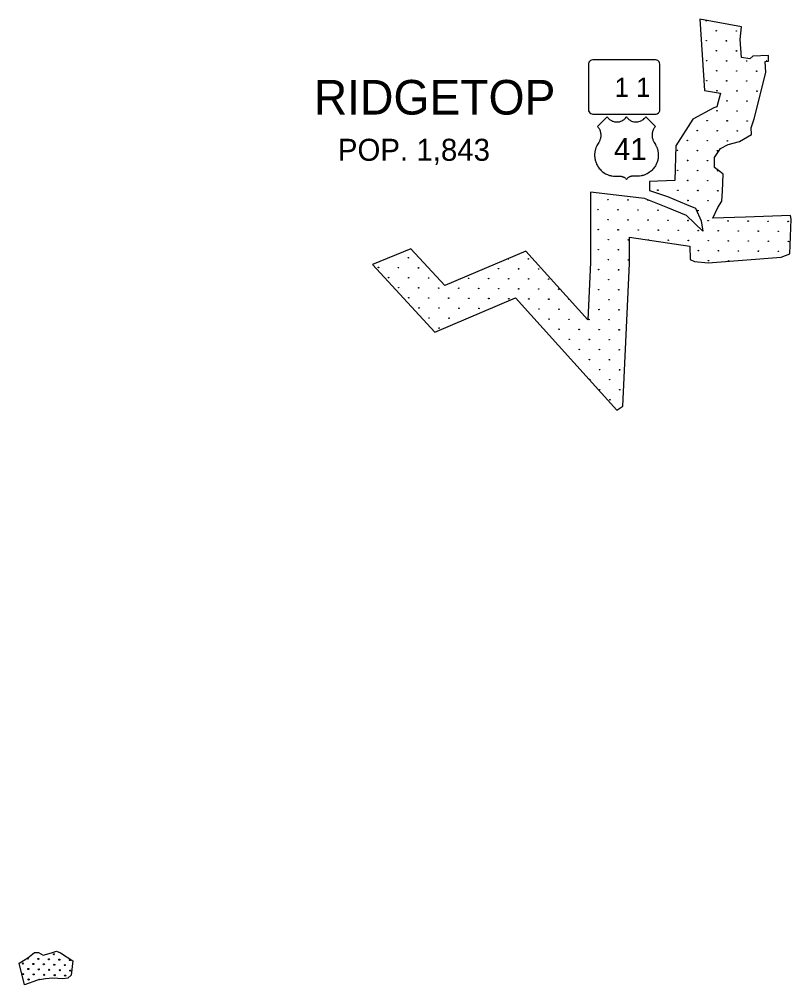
# Model space of a CAD drawing. Extents: x 1612280 to 1883141, y 560852 to 780851.
# Drawn here: x 1730295 to 1745083, y 736836 to 755396 of the extents above; entities that cross this region are included whole.
import ezdxf

# ---------------------------------------------------------------- set-up
doc = ezdxf.new("R2010")
doc.units = 0
for name, color, linetype in [('DESIGN - EROSION CONTROL - Devices', 7, 'Continuous'), ('DESIGN - ROW - Slope Lines', 7, 'Continuous'), ('DESIGN - SCRATCH - User 1', 7, 'Continuous'), ('DESIGN - TRAFFIC CONTROL PERMANENT - Pavement Marking Text', 7, 'Continuous'), ('SURVEY - DRAINAGE - Bridge Deck with Text', 7, 'Continuous'), ('SURVEY - VEGETATION - Features with Text', 7, 'Continuous')]:
    doc.layers.add(name, color=color, linetype=linetype)

msp = doc.modelspace()

# ---------------------------------------------------------------- linework, layer by layer
at = {"layer": 'DESIGN - EROSION CONTROL - Devices'}
for centre in [(1743691, 755176), (1743691, 755176), (1744076, 755172), (1744076, 755172), (1743501, 754986), (1743501, 754986), (1743886, 754982), (1743886, 754982), (1743695, 754791), (1743695, 754791), (1744080, 754788), (1744080, 754788), (1743505, 754601), (1743505, 754601), (1743889, 754597), (1743889, 754597), (1744274, 754594), (1744274, 754594), (1743699, 754407), (1743699, 754407), (1744084, 754403), (1744084, 754403), (1744468, 754399), (1744468, 754399), (1743509, 754217), (1743509, 754217), (1743893, 754213), (1743893, 754213), (1744278, 754209), (1744278, 754209), (1743703, 754022), (1743703, 754022), (1744087, 754019), (1744087, 754019), (1744472, 754015), (1744472, 754015), (1743897, 753828), (1743897, 753828), (1744281, 753824), (1744281, 753824), (1743706, 753638), (1743706, 753638), (1744091, 753634), (1744091, 753634), (1743516, 753447), (1743516, 753447), (1743901, 753444), (1743901, 753444), (1744285, 753440), (1744285, 753440), (1743326, 753257), (1743326, 753257), (1743710, 753253), (1743710, 753253), (1744095, 753250), (1744095, 753250), (1743135, 753067), (1743135, 753067), (1743520, 753063), (1743520, 753063), (1743904, 753059), (1743904, 753059), (1742945, 752876), (1742945, 752876), (1743329, 752872), (1743329, 752872), (1743714, 752869), (1743714, 752869), (1743139, 752682), (1743139, 752682), (1743523, 752678), (1743523, 752678), (1742949, 752492), (1742949, 752492), (1743333, 752488), (1743333, 752488), (1743718, 752484), (1743718, 752484), (1743143, 752297), (1743143, 752297), (1743527, 752294), (1743527, 752294), (1742568, 752111), (1742568, 752111), (1742952, 752107), (1742952, 752107), (1743337, 752103), (1743337, 752103), (1743721, 752100), (1743721, 752100), (1741608, 751928), (1741608, 751928), (1741993, 751924), (1741993, 751924), (1743146, 751913), (1743146, 751913), (1743531, 751909), (1743531, 751909), (1741418, 751737), (1741418, 751737), (1741802, 751734), (1741802, 751734), (1742187, 751730), (1742187, 751730), (1742571, 751726), (1742571, 751726), (1743341, 751719), (1743341, 751719), (1741612, 751543), (1741612, 751543), (1741996, 751540), (1741996, 751540), (1742381, 751536), (1742381, 751536), (1742766, 751532), (1742766, 751532), (1743150, 751528), (1743150, 751528), (1743535, 751525), (1743535, 751525), (1743919, 751521), (1743919, 751521), (1744304, 751517), (1744304, 751517), (1741422, 751353), (1741422, 751353), (1741806, 751349), (1741806, 751349), (1742191, 751345), (1742191, 751345), (1742575, 751342), (1742575, 751342), (1742960, 751338), (1742960, 751338), (1743344, 751334), (1743344, 751334), (1743729, 751331), (1743729, 751331), (1744688, 751513), (1744688, 751513), (1745073, 751510), (1745073, 751510), (1741616, 751159), (1741616, 751159), (1742000, 751155), (1742000, 751155), (1742769, 751148), (1742769, 751148), (1744113, 751327), (1744113, 751327), (1744498, 751323), (1744498, 751323), (1744882, 751319), (1744882, 751319), (1741425, 750968), (1741425, 750968), (1741810, 750965), (1741810, 750965), (1743154, 751144), (1743154, 751144), (1743538, 751140), (1743538, 751140), (1743923, 751136), (1743923, 751136), (1744308, 751133), (1744308, 751133), (1744692, 751129), (1744692, 751129), (1745077, 751125), (1745077, 751125), (1737774, 750812), (1737774, 750812), (1740081, 750789), (1740081, 750789), (1741619, 750774), (1741619, 750774), (1743348, 750950), (1743348, 750950), (1743733, 750946), (1743733, 750946), (1744117, 750942), (1744117, 750942), (1744502, 750938), (1744502, 750938), (1744886, 750935), (1744886, 750935), (1737199, 750625), (1737199, 750625), (1737583, 750621), (1737583, 750621), (1737968, 750617), (1737968, 750617), (1739506, 750602), (1739506, 750602), (1739891, 750599), (1739891, 750599), (1740275, 750595), (1740275, 750595), (1742004, 750770), (1742004, 750770), (1743542, 750756), (1743542, 750756), (1743927, 750752), (1743927, 750752), (1737393, 750431), (1737393, 750431), (1737778, 750427), (1737778, 750427), (1738162, 750423), (1738162, 750423), (1738931, 750416), (1738931, 750416), (1739316, 750412), (1739316, 750412), (1739700, 750408), (1739700, 750408), (1740085, 750405), (1740085, 750405), (1741429, 750584), (1741429, 750584), (1741814, 750580), (1741814, 750580), (1737587, 750237), (1737587, 750237), (1737972, 750233), (1737972, 750233), (1738356, 750229), (1738356, 750229), (1738741, 750225), (1738741, 750225), (1739125, 750222), (1739125, 750222), (1739510, 750218), (1739510, 750218), (1740469, 750401), (1740469, 750401), (1741623, 750390), (1741623, 750390), (1737781, 750042), (1737781, 750042), (1738166, 750039), (1738166, 750039), (1738550, 750035), (1738550, 750035), (1738935, 750031), (1738935, 750031), (1739895, 750214), (1739895, 750214), (1740279, 750210), (1740279, 750210), (1740664, 750207), (1740664, 750207), (1741433, 750199), (1741433, 750199), (1741817, 750196), (1741817, 750196), (1737975, 749848), (1737975, 749848), (1739320, 750028), (1739320, 750028), (1739704, 750024), (1739704, 750024), (1740089, 750020), (1740089, 750020), (1740473, 750016), (1740473, 750016), (1740858, 750013), (1740858, 750013), (1741627, 750005), (1741627, 750005), (1738360, 749845), (1738360, 749845), (1738745, 749841), (1738745, 749841), (1739129, 749837), (1739129, 749837), (1740283, 749826), (1740283, 749826), (1740667, 749822), (1740667, 749822), (1741436, 749815), (1741436, 749815), (1741821, 749811), (1741821, 749811), (1738170, 749654), (1738170, 749654), (1738554, 749650), (1738554, 749650), (1740477, 749632), (1740477, 749632), (1740861, 749628), (1740861, 749628), (1741246, 749624), (1741246, 749624), (1741631, 749621), (1741631, 749621), (1738364, 749460), (1738364, 749460), (1740671, 749438), (1740671, 749438), (1741056, 749434), (1741056, 749434), (1741440, 749430), (1741440, 749430), (1741825, 749426), (1741825, 749426), (1740865, 749243), (1740865, 749243), (1741250, 749240), (1741250, 749240), (1741634, 749236), (1741634, 749236), (1741059, 749049), (1741059, 749049), (1741444, 749046), (1741444, 749046), (1741828, 749042), (1741828, 749042), (1741254, 748855), (1741254, 748855), (1741638, 748851), (1741638, 748851), (1741448, 748661), (1741448, 748661), (1741832, 748657), (1741832, 748657), (1741257, 748471), (1741257, 748471), (1741642, 748467), (1741642, 748467), (1741451, 748276), (1741451, 748276), (1741836, 748273), (1741836, 748273), (1741646, 748082), (1741646, 748082)]:
    msp.add_circle(centre, 5.28, dxfattribs=at)
for centre, start, end in [((1743497, 755370), 124.9794, 34.3953), ((1744658, 754590), 346.4464, 212.4916), ((1742377, 751920), 135.8108, 1.6207), ((1742385, 751151), 2.3635, 161.1221), ((1739697, 750793), 175.2551, 50.7454), ((1742008, 750386), 59.5384, 295.1692), ((1741242, 750009), 263.3295, 91.3777)]:
    msp.add_arc(centre, 5.28, start, end, dxfattribs=at)
at = {"layer": 'DESIGN - ROW - Slope Lines'}
for p, q in [((1741233, 754515), (1741233, 753683)), ((1741233, 754515), (1741233, 753683)), ((1742495, 754616), (1741339, 754616)), ((1742495, 754616), (1741339, 754616)), ((1742606, 753685), (1742606, 754505)), ((1742606, 753685), (1742606, 754505)), ((1741340, 753574), (1742496, 753574)), ((1741340, 753574), (1742496, 753574))]:
    msp.add_line(p, q, dxfattribs=at)
for centre, radius, start, end in [((1741446, 754516), 213, 169.2361, 180.3208), ((1741446, 754516), 213, 169.2361, 180.3208), ((1741322, 754528), 89.8, 108.3711, 161.4494), ((1741322, 754528), 89.8, 108.3711, 161.4494), ((1741329, 754456), 160, 86.6485, 102.7002), ((1741329, 754456), 160, 86.6485, 102.7002), ((1742505, 754418), 198, 77.6972, 92.6427), ((1742505, 754418), 198, 77.6972, 92.6427), ((1742517, 754527), 90.3, 20.2625, 70.5274), ((1742517, 754527), 90.3, 20.2625, 70.5274), ((1742353, 754509), 254, 359.0166, 11.1674), ((1742353, 754509), 254, 359.0166, 11.1674), ((1741507, 753683), 274, 179.8527, 189.8963), ((1741507, 753683), 274, 179.8527, 189.8963), ((1741324, 753665), 91.3, 198.5723, 254.4317), ((1741324, 753665), 91.3, 198.5723, 254.4317), ((1741344, 753936), 362, 263.0109, 269.3986), ((1741344, 753936), 362, 263.0109, 269.3986), ((1742507, 754109), 535, 268.8795, 272.9942), ((1742507, 754109), 535, 268.8795, 272.9942), ((1742518, 753662), 89.4, 280.9255, 342.7445), ((1742518, 753662), 89.4, 280.9255, 342.7445), ((1742537, 753654), 68.6, 345.0701, 358.7436), ((1742537, 753654), 68.6, 345.0701, 358.7436), ((1741659, 753690), 947, 357.7373, 359.7127), ((1741659, 753690), 947, 357.7373, 359.7127)]:
    msp.add_arc(centre, radius, start, end, dxfattribs=at)
at = {"layer": 'DESIGN - SCRATCH - User 1'}
for points in [[(1743375, 755396), (1743468, 754029), (1743772, 753975), (1743705, 753711), (1743642, 753694), (1743242, 753478), (1742917, 752965), (1742897, 752294)], [(1743375, 755396), (1743468, 754029), (1743772, 753975), (1743705, 753711), (1743642, 753694), (1743242, 753478), (1742917, 752965), (1742897, 752294)], [(1743654, 752545), (1743660, 752737), (1743770, 752911), (1743921, 752992), (1744136, 753050), (1744368, 753184), (1744362, 753312), (1744420, 753480), (1744646, 754374), (1744629, 754583), (1744698, 754594), (1744698, 754699), (1744397, 754687), (1744339, 754635), (1744176, 754664), (1744153, 755007), (1744176, 755250), (1743375, 755396)], [(1743654, 752545), (1743660, 752737), (1743770, 752911), (1743921, 752992), (1744136, 753050), (1744368, 753184), (1744362, 753312), (1744420, 753480), (1744646, 754374), (1744629, 754583), (1744698, 754594), (1744698, 754699), (1744397, 754687), (1744339, 754635), (1744176, 754664), (1744153, 755007), (1744176, 755250), (1743375, 755396)], [(1742025, 751205), (1743185, 751036), (1743190, 750781), (1743272, 750740), (1743533, 750711), (1744936, 750821), (1745104, 750885), (1745133, 751553), (1745116, 751622), (1744252, 751593), (1743625, 751570), (1743724, 751779), (1743799, 751901), (1743811, 752093), (1743823, 752418), (1743759, 752470), (1743654, 752545)], [(1742025, 751205), (1743185, 751036), (1743190, 750781), (1743272, 750740), (1743533, 750711), (1744936, 750821), (1745104, 750885), (1745133, 751553), (1745116, 751622), (1744252, 751593), (1743625, 751570), (1743724, 751779), (1743799, 751901), (1743811, 752093), (1743823, 752418), (1743759, 752470), (1743654, 752545)], [(1742897, 752294), (1742406, 752276), (1742410, 752105)], [(1742897, 752294), (1742406, 752276), (1742410, 752105)], [(1742410, 752105), (1742753, 751990), (1743122, 751836), (1743291, 751767), (1743399, 751522), (1743432, 751323)], [(1742410, 752105), (1742753, 751990), (1743122, 751836), (1743291, 751767), (1743399, 751522), (1743432, 751323)], [(1741275, 752071), (1741275, 750721), (1741224, 749617), (1740033, 750938)], [(1741275, 752071), (1741275, 750721), (1741224, 749617), (1740033, 750938)], [(1743432, 751323), (1743119, 751625), (1742762, 751773), (1742313, 751948), (1741275, 752071)], [(1743432, 751323), (1743119, 751625), (1742762, 751773), (1742313, 751948), (1741275, 752071)], [(1739834, 750039), (1741777, 747883), (1741898, 747961), (1742025, 750703), (1742025, 751205)], [(1739834, 750039), (1741777, 747883), (1741898, 747961), (1742025, 750703), (1742025, 751205)], [(1737820, 750986), (1737083, 750679)], [(1737820, 750986), (1737083, 750679)], [(1738475, 750277), (1737820, 750986)], [(1738475, 750277), (1737820, 750986)], [(1740033, 750938), (1738475, 750277)], [(1740033, 750938), (1738475, 750277)], [(1737083, 750679), (1738283, 749381)], [(1737083, 750679), (1738283, 749381)], [(1738283, 749381), (1739834, 750039)], [(1738283, 749381), (1739834, 750039)], [(1730295, 737251), (1730457, 737355), (1730585, 737454), (1730665, 737454), (1730754, 737403), (1730916, 737451), (1731012, 737483), (1731089, 737449), (1731326, 737294)], [(1730295, 737251), (1730457, 737355), (1730585, 737454), (1730665, 737454), (1730754, 737403), (1730916, 737451), (1731012, 737483), (1731089, 737449), (1731326, 737294)], [(1730397, 736836), (1730295, 737251)], [(1730397, 736836), (1730295, 737251)], [(1731326, 737294), (1731292, 737017), (1731227, 736961), (1731130, 736947), (1730937, 736959), (1730797, 736949), (1730643, 736920), (1730397, 736836)], [(1731326, 737294), (1731292, 737017), (1731227, 736961), (1731130, 736947), (1730937, 736959), (1730797, 736949), (1730643, 736920), (1730397, 736836)]]:
    msp.add_lwpolyline(points, dxfattribs=at)
msp.add_arc((1731162, 737413), 10.6, 224.4965, 249.1768, dxfattribs=at)
at = {"layer": 'DESIGN - TRAFFIC CONTROL PERMANENT - Pavement Marking Text'}
for centre in [(1730961, 737421), (1730961, 737421), (1730363, 737242), (1730363, 737242), (1730460, 737339), (1730460, 737339), (1730565, 737234), (1730565, 737234), (1730662, 737331), (1730662, 737331), (1730767, 737227), (1730767, 737227), (1730864, 737324), (1730864, 737324), (1730968, 737219), (1730968, 737219), (1731065, 737316), (1731065, 737316), (1731267, 737309), (1731267, 737309), (1730371, 737040), (1730371, 737040), (1730468, 737137), (1730468, 737137), (1730669, 737130), (1730669, 737130), (1730871, 737122), (1730871, 737122), (1731073, 737115), (1731073, 737115), (1731170, 737212), (1731170, 737212), (1731274, 737107), (1731274, 737107), (1730475, 736935), (1730475, 736935), (1730572, 737033), (1730572, 737033), (1730774, 737025), (1730774, 737025), (1730976, 737018), (1730976, 737018), (1731177, 737010), (1731177, 737010)]:
    msp.add_circle(centre, 10.6, dxfattribs=at)
for centre, start, end in [((1730557, 737436), 233.0295, 22.4541), ((1730677, 736928), 1.938, 199.3172)]:
    msp.add_arc(centre, 10.6, start, end, dxfattribs=at)
at = {"layer": 'SURVEY - DRAINAGE - Bridge Deck with Text'}
for points in [[(1741407, 753337), (1741594, 753523), (1741604, 753509), (1741616, 753495), (1741628, 753482), (1741639, 753473), (1741652, 753463), (1741665, 753455), (1741677, 753448), (1741692, 753441), (1741705, 753436), (1741721, 753430), (1741737, 753427), (1741753, 753424), (1741771, 753423), (1741779, 753423), (1741787, 753423), (1741795, 753423), (1741805, 753424), (1741815, 753426), (1741829, 753428), (1741841, 753431), (1741860, 753437), (1741877, 753445), (1741893, 753454), (1741907, 753463), (1741921, 753473), (1741934, 753485), (1741946, 753498), (1741957, 753512), (1741965, 753523), (1741972, 753513), (1741981, 753502), (1741989, 753493), (1741998, 753484), (1742010, 753473), (1742022, 753464), (1742035, 753455), (1742049, 753447), (1742065, 753440), (1742084, 753433), (1742105, 753427), (1742126, 753424), (1742144, 753423), (1742164, 753423), (1742184, 753425), (1742204, 753429), (1742226, 753436), (1742244, 753443), (1742259, 753451), (1742276, 753461), (1742290, 753472), (1742306, 753486), (1742317, 753497), (1742326, 753509), (1742336, 753523), (1742523, 753337)], [(1741407, 753337), (1741594, 753523), (1741604, 753509), (1741616, 753495), (1741628, 753482), (1741639, 753473), (1741652, 753463), (1741665, 753455), (1741677, 753448), (1741692, 753441), (1741705, 753436), (1741721, 753430), (1741737, 753427), (1741753, 753424), (1741771, 753423), (1741779, 753423), (1741787, 753423), (1741795, 753423), (1741805, 753424), (1741815, 753426), (1741829, 753428), (1741841, 753431), (1741860, 753437), (1741877, 753445), (1741893, 753454), (1741907, 753463), (1741921, 753473), (1741934, 753485), (1741946, 753498), (1741957, 753512), (1741965, 753523), (1741972, 753513), (1741981, 753502), (1741989, 753493), (1741998, 753484), (1742010, 753473), (1742022, 753464), (1742035, 753455), (1742049, 753447), (1742065, 753440), (1742084, 753433), (1742105, 753427), (1742126, 753424), (1742144, 753423), (1742164, 753423), (1742184, 753425), (1742204, 753429), (1742226, 753436), (1742244, 753443), (1742259, 753451), (1742276, 753461), (1742290, 753472), (1742306, 753486), (1742317, 753497), (1742326, 753509), (1742336, 753523), (1742523, 753337)], [(1741407, 753337), (1741416, 753326), (1741424, 753315), (1741432, 753304), (1741438, 753294), (1741445, 753281), (1741451, 753268), (1741457, 753254), (1741462, 753238), (1741466, 753224), (1741469, 753208), (1741471, 753190), (1741472, 753168), (1741472, 753152), (1741471, 753136), (1741469, 753122), (1741465, 753104), (1741461, 753090), (1741456, 753077), (1741451, 753065), (1741446, 753054), (1741439, 753041), (1741431, 753028), (1741421, 753010), (1741408, 752989), (1741404, 752983), (1741399, 752972), (1741392, 752959), (1741388, 752950), (1741383, 752939), (1741379, 752928), (1741375, 752917), (1741371, 752906), (1741367, 752893), (1741364, 752880), (1741361, 752868), (1741359, 752856), (1741357, 752844), (1741355, 752832), (1741354, 752820), (1741353, 752809), (1741353, 752798), (1741353, 752787), (1741353, 752774), (1741353, 752763), (1741354, 752748), (1741356, 752733), (1741358, 752718), (1741361, 752703), (1741365, 752687), (1741370, 752668), (1741375, 752653), (1741381, 752635), (1741387, 752622), (1741392, 752610), (1741399, 752595), (1741409, 752578), (1741418, 752563), (1741430, 752546), (1741443, 752529), (1741457, 752513), (1741471, 752498), (1741484, 752486), (1741501, 752471), (1741520, 752456), (1741544, 752439), (1741565, 752428), (1741584, 752418), (1741602, 752410), (1741623, 752402), (1741642, 752395), (1741662, 752390), (1741672, 752388), (1741684, 752386), (1741714, 752383), (1741820, 752380), (1741868, 752378), (1741872, 752377), (1741877, 752376), (1741882, 752375), (1741887, 752373), (1741892, 752372), (1741896, 752370), (1741902, 752368), (1741906, 752366), (1741911, 752363), (1741915, 752361), (1741919, 752359), (1741928, 752354), (1741937, 752347), (1741945, 752339), (1741953, 752332), (1741959, 752325), (1741965, 752316)], [(1741407, 753337), (1741416, 753326), (1741424, 753315), (1741432, 753304), (1741438, 753294), (1741445, 753281), (1741451, 753268), (1741457, 753254), (1741462, 753238), (1741466, 753224), (1741469, 753208), (1741471, 753190), (1741472, 753168), (1741472, 753152), (1741471, 753136), (1741469, 753122), (1741465, 753104), (1741461, 753090), (1741456, 753077), (1741451, 753065), (1741446, 753054), (1741439, 753041), (1741431, 753028), (1741421, 753010), (1741408, 752989), (1741404, 752983), (1741399, 752972), (1741392, 752959), (1741388, 752950), (1741383, 752939), (1741379, 752928), (1741375, 752917), (1741371, 752906), (1741367, 752893), (1741364, 752880), (1741361, 752868), (1741359, 752856), (1741357, 752844), (1741355, 752832), (1741354, 752820), (1741353, 752809), (1741353, 752798), (1741353, 752787), (1741353, 752774), (1741353, 752763), (1741354, 752748), (1741356, 752733), (1741358, 752718), (1741361, 752703), (1741365, 752687), (1741370, 752668), (1741375, 752653), (1741381, 752635), (1741387, 752622), (1741392, 752610), (1741399, 752595), (1741409, 752578), (1741418, 752563), (1741430, 752546), (1741443, 752529), (1741457, 752513), (1741471, 752498), (1741484, 752486), (1741501, 752471), (1741520, 752456), (1741544, 752439), (1741565, 752428), (1741584, 752418), (1741602, 752410), (1741623, 752402), (1741642, 752395), (1741662, 752390), (1741672, 752388), (1741684, 752386), (1741714, 752383), (1741820, 752380), (1741868, 752378), (1741872, 752377), (1741877, 752376), (1741882, 752375), (1741887, 752373), (1741892, 752372), (1741896, 752370), (1741902, 752368), (1741906, 752366), (1741911, 752363), (1741915, 752361), (1741919, 752359), (1741928, 752354), (1741937, 752347), (1741945, 752339), (1741953, 752332), (1741959, 752325), (1741965, 752316)], [(1742523, 753337), (1742514, 753326), (1742506, 753315), (1742498, 753304), (1742492, 753294), (1742485, 753282), (1742479, 753268), (1742473, 753254), (1742468, 753238), (1742464, 753224), (1742461, 753208), (1742459, 753190), (1742458, 753168), (1742458, 753152), (1742459, 753136), (1742461, 753122), (1742465, 753104), (1742469, 753090), (1742474, 753077), (1742479, 753065), (1742483, 753054), (1742491, 753041), (1742498, 753028), (1742509, 753010), (1742522, 752989), (1742525, 752983), (1742531, 752972), (1742538, 752959), (1742542, 752950), (1742547, 752939), (1742551, 752928), (1742555, 752917), (1742559, 752906), (1742563, 752893), (1742566, 752880), (1742569, 752868), (1742571, 752856), (1742573, 752844), (1742575, 752832), (1742576, 752820), (1742577, 752809), (1742577, 752798), (1742577, 752787), (1742577, 752774), (1742577, 752763), (1742576, 752748), (1742574, 752733), (1742572, 752718), (1742569, 752703), (1742565, 752687), (1742560, 752668), (1742555, 752653), (1742549, 752635), (1742543, 752622), (1742538, 752610), (1742531, 752595), (1742521, 752578), (1742512, 752563), (1742500, 752546), (1742487, 752529), (1742473, 752513), (1742459, 752498), (1742446, 752486), (1742429, 752471), (1742410, 752456), (1742385, 752439), (1742365, 752428), (1742346, 752418), (1742328, 752410), (1742307, 752402), (1742288, 752395), (1742268, 752390), (1742258, 752388), (1742246, 752386), (1742216, 752383), (1742110, 752380), (1742062, 752378), (1742058, 752377), (1742053, 752376), (1742048, 752375), (1742043, 752373), (1742038, 752372), (1742034, 752370), (1742028, 752368), (1742024, 752366), (1742019, 752363), (1742015, 752361), (1742011, 752359), (1742002, 752354), (1741993, 752347), (1741985, 752339), (1741977, 752332), (1741971, 752325), (1741965, 752316)], [(1742523, 753337), (1742514, 753326), (1742506, 753315), (1742498, 753304), (1742492, 753294), (1742485, 753282), (1742479, 753268), (1742473, 753254), (1742468, 753238), (1742464, 753224), (1742461, 753208), (1742459, 753190), (1742458, 753168), (1742458, 753152), (1742459, 753136), (1742461, 753122), (1742465, 753104), (1742469, 753090), (1742474, 753077), (1742479, 753065), (1742483, 753054), (1742491, 753041), (1742498, 753028), (1742509, 753010), (1742522, 752989), (1742525, 752983), (1742531, 752972), (1742538, 752959), (1742542, 752950), (1742547, 752939), (1742551, 752928), (1742555, 752917), (1742559, 752906), (1742563, 752893), (1742566, 752880), (1742569, 752868), (1742571, 752856), (1742573, 752844), (1742575, 752832), (1742576, 752820), (1742577, 752809), (1742577, 752798), (1742577, 752787), (1742577, 752774), (1742577, 752763), (1742576, 752748), (1742574, 752733), (1742572, 752718), (1742569, 752703), (1742565, 752687), (1742560, 752668), (1742555, 752653), (1742549, 752635), (1742543, 752622), (1742538, 752610), (1742531, 752595), (1742521, 752578), (1742512, 752563), (1742500, 752546), (1742487, 752529), (1742473, 752513), (1742459, 752498), (1742446, 752486), (1742429, 752471), (1742410, 752456), (1742385, 752439), (1742365, 752428), (1742346, 752418), (1742328, 752410), (1742307, 752402), (1742288, 752395), (1742268, 752390), (1742258, 752388), (1742246, 752386), (1742216, 752383), (1742110, 752380), (1742062, 752378), (1742058, 752377), (1742053, 752376), (1742048, 752375), (1742043, 752373), (1742038, 752372), (1742034, 752370), (1742028, 752368), (1742024, 752366), (1742019, 752363), (1742015, 752361), (1742011, 752359), (1742002, 752354), (1741993, 752347), (1741985, 752339), (1741977, 752332), (1741971, 752325), (1741965, 752316)]]:
    msp.add_lwpolyline(points, dxfattribs=at)

# ---------------------------------------------------------------- texts
at = {"layer": 'DESIGN - ROW - Slope Lines'}
msp.add_text('1 1', height=369.6, rotation=0.0012, dxfattribs=at).set_placement((1741738, 753904))
msp.add_text('1 1', height=369.6, rotation=0.0012, dxfattribs=at).set_placement((1741738, 753904))
at = {"layer": 'SURVEY - DRAINAGE - Bridge Deck with Text'}
msp.add_text('41', height=422.4, rotation=0.0013, dxfattribs=at).set_placement((1741724, 752689))
msp.add_text('41', height=422.4, rotation=0.0013, dxfattribs=at).set_placement((1741724, 752689))
at = {"layer": 'SURVEY - VEGETATION - Features with Text'}
for s, height, p in [('RIDGETOP', 665, (1735955, 753565)), ('RIDGETOP', 665, (1735955, 753565)), ('RIDGETOP', 665, (1735955, 753565)), ('RIDGETOP', 665, (1735955, 753565)), ('RIDGETOP', 665, (1735955, 753565)), ('RIDGETOP', 665, (1735955, 753565)), ('RIDGETOP', 665, (1735955, 753565)), ('RIDGETOP', 665, (1735955, 753565)), ('RIDGETOP', 665, (1735955, 753565)), ('RIDGETOP', 665, (1735955, 753565)), ('RIDGETOP', 665, (1735955, 753565)), ('RIDGETOP', 665, (1735955, 753565)), ('RIDGETOP', 665, (1735955, 753565)), ('RIDGETOP', 665, (1735955, 753565)), ('RIDGETOP', 665, (1735955, 753565)), ('RIDGETOP', 665, (1735955, 753565)), ('RIDGETOP', 665, (1735955, 753565)), ('RIDGETOP', 665, (1735955, 753565)), ('RIDGETOP', 665, (1735955, 753565)), ('RIDGETOP', 665, (1735955, 753565)), ('RIDGETOP', 665, (1735955, 753565)), ('RIDGETOP', 665, (1735955, 753565)), ('RIDGETOP', 665, (1735955, 753565)), ('RIDGETOP', 665, (1735955, 753565)), ('RIDGETOP', 665, (1735955, 753565)), ('RIDGETOP', 665, (1735955, 753565)), ('RIDGETOP', 665, (1735955, 753565)), ('RIDGETOP', 665, (1735955, 753565)), ('RIDGETOP', 665, (1735955, 753565)), ('RIDGETOP', 665, (1735955, 753565)), ('RIDGETOP', 665, (1735955, 753565)), ('RIDGETOP', 665, (1735955, 753565)), ('POP. 1,843', 423, (1736418, 752676)), ('POP. 1,843', 423, (1736418, 752676)), ('POP. 1,843', 423, (1736418, 752676)), ('POP. 1,843', 423, (1736418, 752676)), ('POP. 1,843', 423, (1736418, 752676)), ('POP. 1,843', 423, (1736418, 752676)), ('POP. 1,843', 423, (1736418, 752676)), ('POP. 1,843', 423, (1736418, 752676)), ('POP. 1,843', 423, (1736418, 752676)), ('POP. 1,843', 423, (1736418, 752676)), ('POP. 1,843', 423, (1736418, 752676)), ('POP. 1,843', 423, (1736418, 752676)), ('POP. 1,843', 423, (1736418, 752676)), ('POP. 1,843', 423, (1736418, 752676)), ('POP. 1,843', 423, (1736418, 752676)), ('POP. 1,843', 423, (1736418, 752676)), ('POP. 1,843', 423, (1736418, 752676)), ('POP. 1,843', 423, (1736418, 752676)), ('POP. 1,843', 423, (1736418, 752676)), ('POP. 1,843', 423, (1736418, 752676)), ('POP. 1,843', 423, (1736418, 752676)), ('POP. 1,843', 423, (1736418, 752676)), ('POP. 1,843', 423, (1736418, 752676)), ('POP. 1,843', 423, (1736418, 752676)), ('POP. 1,843', 423, (1736418, 752676)), ('POP. 1,843', 423, (1736418, 752676)), ('POP. 1,843', 423, (1736418, 752676)), ('POP. 1,843', 423, (1736418, 752676)), ('POP. 1,843', 423, (1736418, 752676)), ('POP. 1,843', 423, (1736418, 752676)), ('POP. 1,843', 423, (1736418, 752676)), ('POP. 1,843', 423, (1736418, 752676))]:
    msp.add_text(s, height=height, rotation=0, dxfattribs=at).set_placement(p)

doc.saveas('drawing.dxf')
